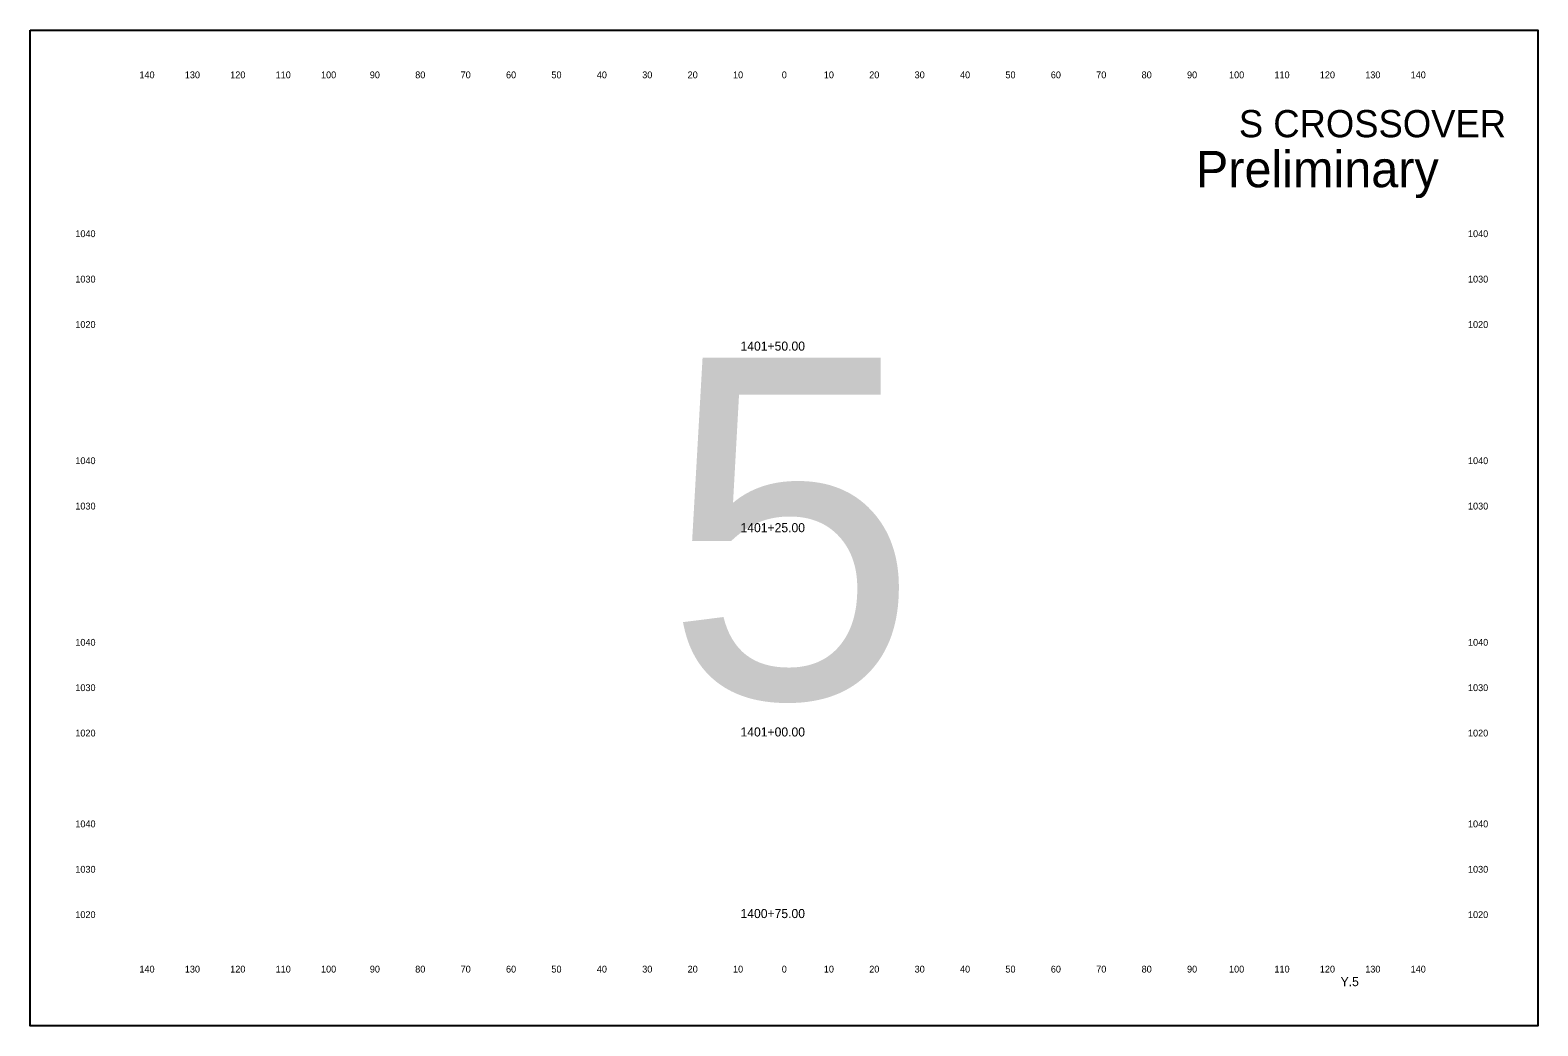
# Model space of a CAD drawing. Extents: x 10123 to 14768, y 9730 to 9950.
# Drawn here: x 11563.2 to 11895.3, y 9730.3 to 9949.6 of the extents above; entities that cross this region are included whole.
import ezdxf

# ---------------------------------------------------------------- set-up
doc = ezdxf.new("R2010")
doc.units = 0
for name, color, linetype in [('dsnTextCpn', 7, 'Continuous'), ('dsnTextCpnTitleSheetLocDesc', 7, 'Continuous'), ('dsnTextCpnTitleSheetPIN', 7, 'Continuous'), ('dsnTextCpnTitleSheetWorkType', 7, 'Continuous')]:
    doc.layers.add(name, color=color, linetype=linetype)

msp = doc.modelspace()

# ---------------------------------------------------------------- linework, layer by layer
at = {"layer": 'dsnTextCpnTitleSheetWorkType'}
msp.add_lwpolyline([(11563.21, 9949.6), (11895.29, 9949.6), (11895.29, 9730.26), (11563.21, 9730.26)], close=True, dxfattribs=at)

# ---------------------------------------------------------------- texts
at = {"layer": 'dsnTextCpn'}
for s, height, p in [('140', 1.5, (11587.27, 9939)), ('130', 1.5, (11597.27, 9939)), ('120', 1.5, (11607.27, 9939)), ('110', 1.5, (11617.27, 9939)), ('100', 1.5, (11627.27, 9939)), ('90', 1.5, (11638.02, 9939)), ('80', 1.5, (11648.02, 9939)), ('70', 1.5, (11658.02, 9939)), ('60', 1.5, (11668.02, 9939)), ('50', 1.5, (11678.02, 9939)), ('40', 1.5, (11688.02, 9939)), ('30', 1.5, (11698.02, 9939)), ('20', 1.5, (11708.02, 9939)), ('10', 1.5, (11718.02, 9939)), ('0', 1.5, (11728.76, 9939)), ('0', 1.5, (11728.76, 9939)), ('10', 1.5, (11738.02, 9939)), ('20', 1.5, (11748.02, 9939)), ('30', 1.5, (11758.02, 9939)), ('40', 1.5, (11768.02, 9939)), ('50', 1.5, (11778.02, 9939)), ('60', 1.5, (11788.02, 9939)), ('70', 1.5, (11798.02, 9939)), ('80', 1.5, (11808.02, 9939)), ('90', 1.5, (11818.02, 9939)), ('100', 1.5, (11827.27, 9939)), ('110', 1.5, (11837.27, 9939)), ('120', 1.5, (11847.27, 9939)), ('130', 1.5, (11857.27, 9939)), ('140', 1.5, (11867.27, 9939)), ('S CROSSOVER', 6, (11829.44, 9926)), ('1040', 1.5, (11573.15, 9904)), ('1040', 1.5, (11879.9, 9904)), ('1030', 1.5, (11573.15, 9894)), ('1030', 1.5, (11879.9, 9894)), ('1020', 1.5, (11573.15, 9884)), ('1020', 1.5, (11879.9, 9884)), ('1401+50.00', 2, (11719.67, 9879)), ('1040', 1.5, (11573.15, 9854)), ('1040', 1.5, (11879.9, 9854)), ('1030', 1.5, (11573.15, 9844)), ('1030', 1.5, (11879.9, 9844)), ('1401+25.00', 2, (11719.67, 9839)), ('1040', 1.5, (11573.15, 9814)), ('1040', 1.5, (11879.9, 9814)), ('1030', 1.5, (11573.15, 9804)), ('1030', 1.5, (11879.9, 9804)), ('1020', 1.5, (11573.15, 9794)), ('1401+00.00', 2, (11719.67, 9794)), ('1020', 1.5, (11879.9, 9794)), ('1040', 1.5, (11573.15, 9774)), ('1040', 1.5, (11879.9, 9774)), ('1030', 1.5, (11573.15, 9764)), ('1030', 1.5, (11879.9, 9764)), ('1020', 1.5, (11573.15, 9754)), ('1400+75.00', 2, (11719.67, 9754)), ('1020', 1.5, (11879.9, 9754)), ('140', 1.5, (11587.27, 9742)), ('130', 1.5, (11597.27, 9742)), ('120', 1.5, (11607.27, 9742)), ('110', 1.5, (11617.27, 9742)), ('100', 1.5, (11627.27, 9742)), ('90', 1.5, (11638.02, 9742)), ('80', 1.5, (11648.02, 9742)), ('70', 1.5, (11658.02, 9742)), ('60', 1.5, (11668.02, 9742)), ('50', 1.5, (11678.02, 9742)), ('40', 1.5, (11688.02, 9742)), ('30', 1.5, (11698.02, 9742)), ('20', 1.5, (11708.02, 9742)), ('10', 1.5, (11718.02, 9742)), ('0', 1.5, (11728.76, 9742)), ('0', 1.5, (11728.76, 9742)), ('10', 1.5, (11738.02, 9742)), ('20', 1.5, (11748.02, 9742)), ('30', 1.5, (11758.02, 9742)), ('40', 1.5, (11768.02, 9742)), ('50', 1.5, (11778.02, 9742)), ('60', 1.5, (11788.02, 9742)), ('70', 1.5, (11798.02, 9742)), ('80', 1.5, (11808.02, 9742)), ('90', 1.5, (11818.02, 9742)), ('100', 1.5, (11827.27, 9742)), ('110', 1.5, (11837.27, 9742)), ('120', 1.5, (11847.27, 9742)), ('130', 1.5, (11857.27, 9742)), ('140', 1.5, (11867.27, 9742))]:
    msp.add_text(s, height=height, dxfattribs=at).set_placement(p)
at = {"layer": 'dsnTextCpnTitleSheetLocDesc'}
msp.add_text('Preliminary', height=8, dxfattribs=at).set_placement((11819.97, 9915))
at = {"layer": 'dsnTextCpnTitleSheetPIN'}
msp.add_text('Y.5', height=2, dxfattribs=at).set_placement((11851.85, 9739))
at = {"layer": 'dsnTextCpnTitleSheetWorkType'}
msp.add_text('5', height=75, dxfattribs=at).set_placement((11702.99, 9802.43))

doc.saveas('drawing.dxf')
